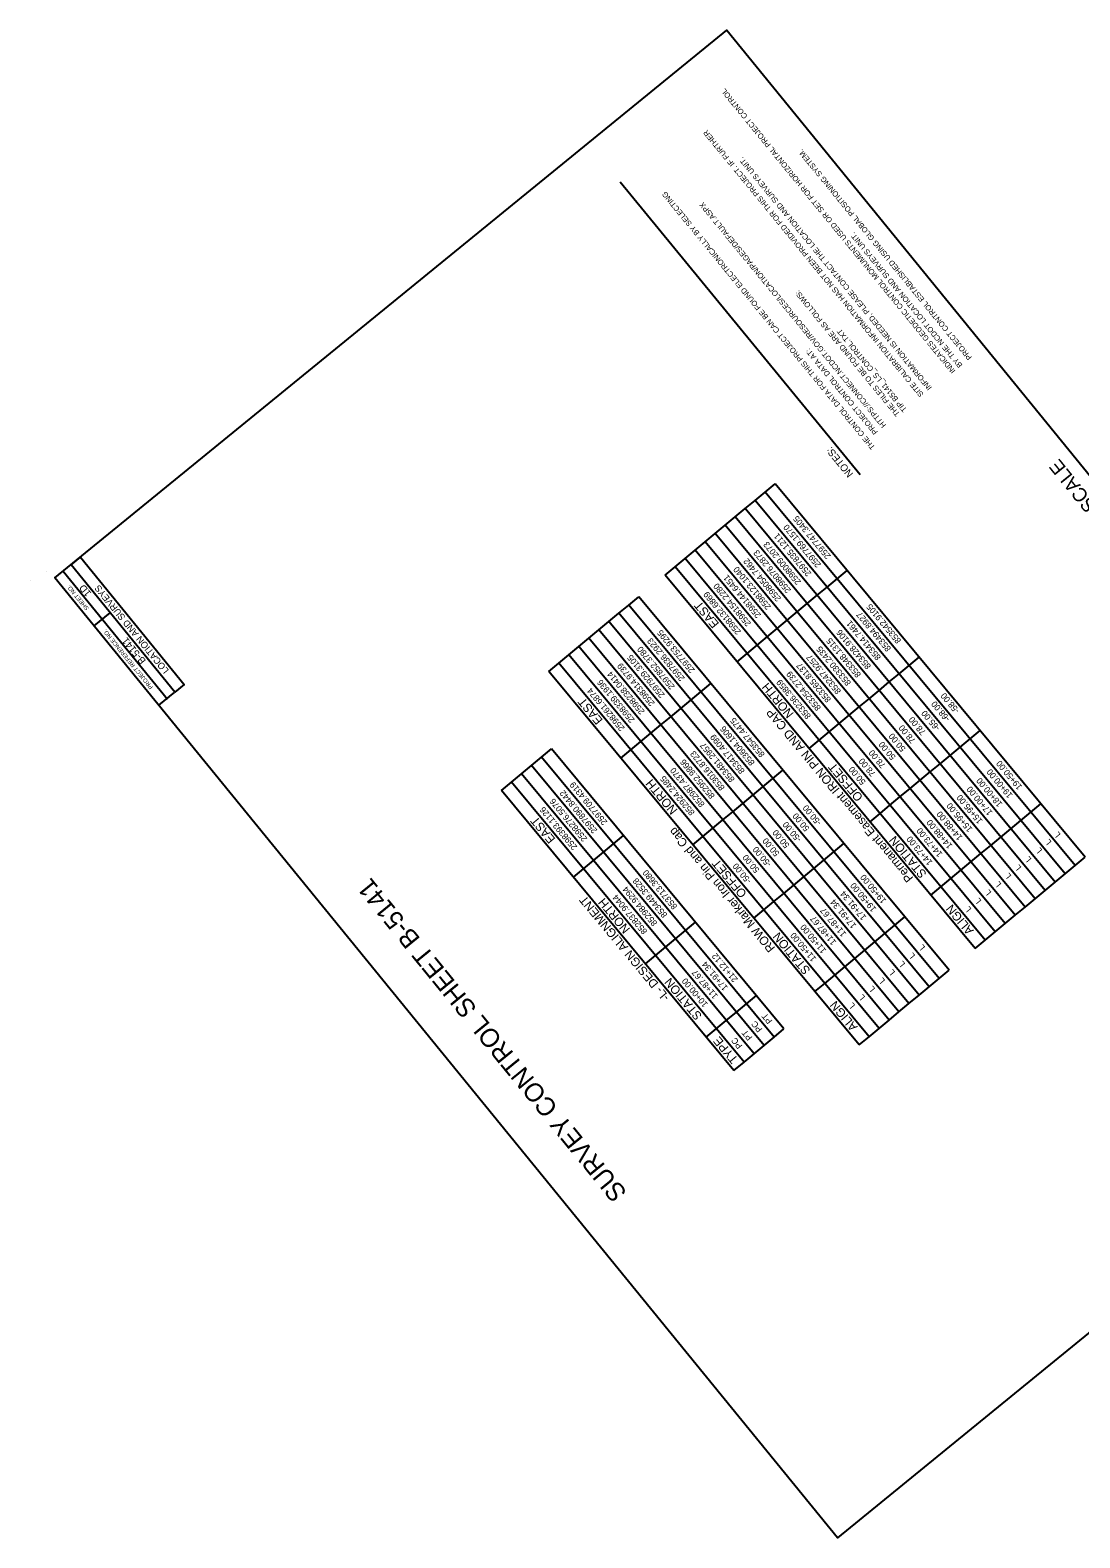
# Model space of a CAD drawing. Extents: x 2596159 to 2598075, y 851667 to 853493.
# Drawn here: x 2596159 to 2597430, y 851667 to 853493 of the extents above; entities that cross this region are included whole.
import ezdxf

# ---------------------------------------------------------------- set-up
doc = ezdxf.new("R2010")
doc.units = 0
for name, color, linetype in [('CTL Sheet Notes CELL', 7, 'Continuous'), ('CTL Sheet Table Cell', 7, 'Continuous'), ('CTL Sheet Text', 7, 'Continuous'), ('Old_Level_1', 7, 'Continuous'), ('Old_Level_18', 7, 'Continuous'), ('Old_Level_40', 7, 'Continuous'), ('Old_Level_44', 7, 'Continuous'), ('Old_Level_50', 7, 'Continuous'), ('Old_Level_52', 7, 'Continuous')]:
    doc.layers.add(name, color=color, linetype=linetype)

msp = doc.modelspace()

# ---------------------------------------------------------------- linework, layer by layer
at = {"layer": 'CTL Sheet Notes CELL'}
msp.add_line((2597164.2, 852954.1), (2596873.5, 853308.6), dxfattribs=at)
at = {"layer": 'CTL Sheet Table Cell'}
for p, q in [((2597049.3, 852933.3), (2597061.4, 852943.4)), ((2597437, 852491), (2597061.4, 852943.4)), ((2597025, 852913.2), (2597037.2, 852923.2)), ((2597037.2, 852923.2), (2597049.3, 852933.3)), ((2597412.8, 852470.9), (2597037.2, 852923.2)), ((2597424.9, 852480.9), (2597049.3, 852933.3)), ((2597000.8, 852893.1), (2597012.9, 852903.1)), ((2597012.9, 852903.1), (2597025, 852913.2)), ((2597388.6, 852450.8), (2597012.9, 852903.1)), ((2597400.7, 852460.8), (2597025, 852913.2)), ((2596976.6, 852872.9), (2596988.7, 852883)), ((2596988.7, 852883), (2597000.8, 852893.1)), ((2597364.3, 852430.6), (2596988.7, 852883)), ((2597376.5, 852440.7), (2597000.8, 852893.1)), ((2596952.3, 852852.8), (2596964.5, 852862.9)), ((2596964.5, 852862.9), (2596976.6, 852872.9)), ((2597340.1, 852410.5), (2596964.5, 852862.9)), ((2597352.2, 852420.6), (2596976.6, 852872.9)), ((2596940.2, 852842.8), (2596952.3, 852852.8)), ((2597328, 852400.5), (2596952.3, 852852.8)), ((2596928.1, 852832.7), (2596940.2, 852842.8)), ((2597303.8, 852380.3), (2596928.1, 852832.7)), ((2597315.9, 852390.4), (2596940.2, 852842.8)), ((2597124.4, 852818.2), (2597136.5, 852828.3)), ((2597136.5, 852828.3), (2597148.6, 852838.4)), ((2597100.1, 852798.1), (2597112.2, 852808.2)), ((2597112.2, 852808.2), (2597124.4, 852818.2)), ((2596872.1, 852786.4), (2596884.2, 852796.4)), ((2596884.2, 852796.4), (2596896.4, 852806.5)), ((2597259.9, 852344), (2596884.2, 852796.4)), ((2597272, 852354.1), (2596896.4, 852806.5)), ((2597088, 852788), (2597100.1, 852798.1)), ((2596847.9, 852766.2), (2596860, 852776.3)), ((2596860, 852776.3), (2596872.1, 852786.4)), ((2597235.7, 852323.9), (2596860, 852776.3)), ((2597247.8, 852334), (2596872.1, 852786.4)), ((2597063.8, 852767.9), (2597075.9, 852778)), ((2597075.9, 852778), (2597088, 852788)), ((2596823.7, 852746.1), (2596835.8, 852756.2)), ((2596835.8, 852756.2), (2596847.9, 852766.2)), ((2597211.4, 852303.8), (2596835.8, 852756.2)), ((2597223.5, 852313.9), (2596847.9, 852766.2)), ((2597039.5, 852747.8), (2597051.7, 852757.9)), ((2597051.7, 852757.9), (2597063.8, 852767.9)), ((2596799.4, 852726), (2596811.5, 852736)), ((2596811.5, 852736), (2596823.7, 852746.1)), ((2597187.2, 852283.7), (2596811.5, 852736)), ((2597199.3, 852293.7), (2596823.7, 852746.1)), ((2597015.3, 852727.7), (2597027.4, 852737.7)), ((2597027.4, 852737.7), (2597039.5, 852747.8)), ((2596787.3, 852715.9), (2596799.4, 852726)), ((2597175.1, 852273.6), (2596799.4, 852726)), ((2597211.6, 852713.2), (2597223.7, 852723.3)), ((2597223.7, 852723.3), (2597235.8, 852733.3)), ((2597163, 852263.6), (2596787.3, 852715.9)), ((2596971.5, 852691.4), (2596983.6, 852701.5)), ((2597187.3, 852693.1), (2597199.4, 852703.2)), ((2597199.4, 852703.2), (2597211.6, 852713.2)), ((2596947.2, 852671.3), (2596959.3, 852681.3)), ((2596959.3, 852681.3), (2596971.5, 852691.4)), ((2597163.1, 852673), (2597175.2, 852683)), ((2597175.2, 852683), (2597187.3, 852693.1)), ((2596935.1, 852661.2), (2596947.2, 852671.3)), ((2597138.9, 852652.8), (2597151, 852662.9)), ((2597151, 852662.9), (2597163.1, 852673)), ((2596910.9, 852641.1), (2596923, 852651.2)), ((2596923, 852651.2), (2596935.1, 852661.2)), ((2597126.7, 852642.8), (2597138.9, 852652.8)), ((2597297.5, 852634.4), (2597309.6, 852644.5)), ((2596886.6, 852621), (2596898.8, 852631)), ((2596898.8, 852631), (2596910.9, 852641.1)), ((2597102.5, 852622.7), (2597114.6, 852632.7)), ((2597114.6, 852632.7), (2597126.7, 852642.8)), ((2597285.4, 852624.4), (2597297.5, 852634.4)), ((2596766.2, 852602.1), (2596778.3, 852612.2)), ((2596778.3, 852612.2), (2596790.4, 852622.2)), ((2597060, 852272.9), (2596778.3, 852612.2)), ((2597072.1, 852283), (2596790.4, 852622.2)), ((2596874.5, 852610.9), (2596886.6, 852621)), ((2597261.1, 852604.2), (2597273.2, 852614.3)), ((2597273.2, 852614.3), (2597285.4, 852624.4)), ((2596741.9, 852582), (2596754, 852592)), ((2596754, 852592), (2596766.2, 852602.1)), ((2597035.8, 852252.8), (2596754, 852592)), ((2597047.9, 852262.8), (2596766.2, 852602.1)), ((2597058.7, 852586.4), (2597070.8, 852596.4)), ((2597236.9, 852584.1), (2597249, 852594.2)), ((2597249, 852594.2), (2597261.1, 852604.2)), ((2596729.8, 852571.9), (2596741.9, 852582)), ((2597011.5, 852232.6), (2596729.8, 852571.9)), ((2597023.7, 852242.7), (2596741.9, 852582)), ((2597034.4, 852566.3), (2597046.5, 852576.3)), ((2597046.5, 852576.3), (2597058.7, 852586.4)), ((2597212.6, 852564), (2597224.8, 852574.1)), ((2597224.8, 852574.1), (2597236.9, 852584.1)), ((2597010.2, 852546.1), (2597022.3, 852556.2)), ((2597022.3, 852556.2), (2597034.4, 852566.3)), ((2597188.4, 852543.9), (2597200.5, 852553.9)), ((2597200.5, 852553.9), (2597212.6, 852564)), ((2597371.3, 852545.6), (2597383.4, 852555.6)), ((2596986, 852526), (2596998.1, 852536.1)), ((2596998.1, 852536.1), (2597010.2, 852546.1)), ((2597176.3, 852533.8), (2597188.4, 852543.9)), ((2597347, 852525.4), (2597359.1, 852535.5)), ((2597359.1, 852535.5), (2597371.3, 852545.6)), ((2596865.5, 852507.2), (2596877.6, 852517.2)), ((2596961.7, 852505.9), (2596973.8, 852516)), ((2596973.8, 852516), (2596986, 852526)), ((2597334.9, 852515.4), (2597347, 852525.4)), ((2596853.4, 852497.1), (2596865.5, 852507.2)), ((2597120.3, 852487.5), (2597132.4, 852497.5)), ((2597132.4, 852497.5), (2597144.6, 852507.6)), ((2597310.7, 852495.3), (2597322.8, 852505.3)), ((2597322.8, 852505.3), (2597334.9, 852515.4)), ((2596829.1, 852477), (2596841.2, 852487)), ((2596841.2, 852487), (2596853.4, 852497.1)), ((2597108.2, 852477.4), (2597120.3, 852487.5)), ((2597286.4, 852475.1), (2597298.6, 852485.2)), ((2597298.6, 852485.2), (2597310.7, 852495.3)), ((2597412.8, 852470.9), (2597424.9, 852480.9)), ((2597424.9, 852480.9), (2597437, 852491)), ((2596817, 852466.9), (2596829.1, 852477)), ((2597084, 852457.3), (2597096.1, 852467.3)), ((2597096.1, 852467.3), (2597108.2, 852477.4)), ((2597262.2, 852455), (2597274.3, 852465.1)), ((2597274.3, 852465.1), (2597286.4, 852475.1)), ((2597388.6, 852450.8), (2597400.7, 852460.8)), ((2597400.7, 852460.8), (2597412.8, 852470.9)), ((2597059.7, 852437.2), (2597071.9, 852447.2)), ((2597071.9, 852447.2), (2597084, 852457.3)), ((2597250.1, 852444.9), (2597262.2, 852455)), ((2597376.5, 852440.7), (2597388.6, 852450.8)), ((2597035.5, 852417), (2597047.6, 852427.1)), ((2597047.6, 852427.1), (2597059.7, 852437.2)), ((2597352.2, 852420.6), (2597364.3, 852430.6)), ((2597364.3, 852430.6), (2597376.5, 852440.7)), ((2596952.7, 852402.1), (2596964.8, 852412.2)), ((2597194.1, 852398.6), (2597206.2, 852408.7)), ((2597206.2, 852408.7), (2597218.3, 852418.7)), ((2597328, 852400.5), (2597340.1, 852410.5)), ((2597340.1, 852410.5), (2597352.2, 852420.6)), ((2596928.5, 852382), (2596940.6, 852392.1)), ((2596940.6, 852392.1), (2596952.7, 852402.1)), ((2597169.9, 852378.5), (2597182, 852388.5)), ((2597182, 852388.5), (2597194.1, 852398.6)), ((2597303.8, 852380.3), (2597315.9, 852390.4)), ((2597315.9, 852390.4), (2597328, 852400.5)), ((2596904.2, 852361.9), (2596916.3, 852372)), ((2596916.3, 852372), (2596928.5, 852382)), ((2597157.8, 852368.4), (2597169.9, 852378.5)), ((2597133.5, 852348.3), (2597145.6, 852358.4)), ((2597145.6, 852358.4), (2597157.8, 852368.4)), ((2597259.9, 852344), (2597272, 852354.1)), ((2597109.3, 852328.2), (2597121.4, 852338.2)), ((2597121.4, 852338.2), (2597133.5, 852348.3)), ((2597235.7, 852323.9), (2597247.8, 852334)), ((2597247.8, 852334), (2597259.9, 852344)), ((2597026.5, 852313.3), (2597038.6, 852323.3)), ((2597223.5, 852313.9), (2597235.7, 852323.9)), ((2597002.2, 852293.2), (2597014.4, 852303.2)), ((2597014.4, 852303.2), (2597026.5, 852313.3)), ((2597199.3, 852293.7), (2597211.4, 852303.8)), ((2597211.4, 852303.8), (2597223.5, 852313.9)), ((2596978, 852273), (2596990.1, 852283.1)), ((2596990.1, 852283.1), (2597002.2, 852293.2)), ((2597060, 852272.9), (2597072.1, 852283)), ((2597175.1, 852273.6), (2597187.2, 852283.7)), ((2597187.2, 852283.7), (2597199.3, 852293.7)), ((2597035.8, 852252.8), (2597047.9, 852262.8)), ((2597047.9, 852262.8), (2597060, 852272.9)), ((2597163, 852263.6), (2597175.1, 852273.6)), ((2597011.5, 852232.6), (2597023.7, 852242.7)), ((2597023.7, 852242.7), (2597035.8, 852252.8))]:
    msp.add_line(p, q, dxfattribs=at)
at = {"layer": 'Old_Level_1'}
msp.add_line((2596179.2, 852837.4), (2596179.2, 852837.4), dxfattribs=at)
at = {"layer": 'Old_Level_18'}
msp.add_lwpolyline([(2596922.8, 851929.1), (2596189, 852829.3), (2597002.9, 853492.7), (2597950.7, 852330), (2597136.8, 851666.6), (2596922.8, 851929.1)], dxfattribs=at)
at = {"layer": 'Old_Level_40'}
for p, q in [((2596325.2, 852682.2), (2596198.8, 852837.2)), ((2596236.5, 852771.2), (2596255.8, 852787)), ((2596314.8, 852675.1), (2596334.1, 852690.9))]:
    msp.add_line(p, q, dxfattribs=at)
msp.add_lwpolyline([(2596334.1, 852690.9), (2596208.5, 852845.1), (2596219.9, 852854.4), (2596345.5, 852700.2)], close=True, dxfattribs=at)
at = {"layer": 'Old_Level_50'}
msp.add_line((2596158.9, 852826.7), (2596158.9, 852826.7), dxfattribs=at)
at = {"layer": 'Old_Level_52'}
msp.add_line((2596179.2, 852837.4), (2596179.2, 852837.4), dxfattribs=at)

# ---------------------------------------------------------------- texts
at = {"layer": 'CTL Sheet Notes CELL'}
for s, height, rotation, p in [('INDICATES GEODETIC CONTROL MONUMENTS USED OR SET FOR HORIZONTAL PROJECT CONTROL', 6.52, 129.2489, (2597280.3, 853080.2)), ('SITE CALIBRATION INFORMATION HAS NOT BEEN PROVIDED FOR THIS PROJECT. IF FURTHER', 6.52, 129.3541, (2597241.7, 853051.7)), ('PROJECT CONTROL ESTABLISHED USING GLOBAL POSITIONING SYSTEM.', 6.52, 129.2489, (2597300.2, 853096.5)), ('INFORMATION IS NEEDED, PLEASE CONTACT THE LOCATION AND SURVEYS UNIT.', 6.52, 129.3541, (2597251.6, 853059.8)), ('   THE CONTROL DATA FOR THIS PROJECT CAN BE FOUND ELECTRONICALLY BY SELECTING', 6.52, 129.3541, (2597187.8, 852982)), ('HTTPS://CONNECT.NCDOT.GOV/RESOURCES/LOCATION/PAGES/DEFAULT.ASPX', 6.52, 129.3541, (2597196.2, 853014.4)), ('BY THE NCDOT LOCATION AND SURVEYS UNIT.', 6.52, 129.2489, (2597288.7, 853087.1)), ('THE FILES TO BE FOUND ARE AS FOLLOWS:', 6.52, 129.3541, (2597212.9, 853028.1)), ('TIP B5141_LS_CONTROL.TXT', 6.52, 129.3541, (2597221.4, 853033.4)), ('PROJECT CONTROL DATA AT:', 6.52, 129.3541, (2597186.2, 853006.2)), ('NOTES:', 8.69, 129.2489, (2597156.5, 852955.4)), ('EAST', 10.5, 129.7067, (2596994, 852773.9)), ('NORTH', 10.5, 129.7067, (2597084.5, 852664.9)), ('EAST', 10.5, 129.7067, (2596853.2, 852657.1)), ('Permanent Easement IRON PIN AND CAP', 10.5, 129.7067, (2597229.3, 852465.9)), ('OFFSET', 10.5, 129.7067, (2597168.4, 852563.9)), ('NORTH', 10.5, 129.7067, (2596943.7, 852548.1)), ('EAST', 10.5, 129.7067, (2596795.7, 852513.1)), ('ROW Marker Iron Pin and Cap', 10.5, 129.7067, (2597061.9, 852381.2)), ('STATION', 10.5, 129.7067, (2597245.5, 852471)), ('OFFSET', 10.5, 129.7067, (2597027.6, 852447.1)), ('-L- DESIGN ALIGNMENT', 10.5, 129.7067, (2596934.1, 852321.8)), ('NORTH', 10.5, 129.7067, (2596886.2, 852404.1)), ('ALIGN', 10.5, 129.7067, (2597302.5, 852402.3)), ('STATION', 10.5, 129.7067, (2597104.7, 852354.3)), ('STATION', 10.5, 129.7067, (2596973.4, 852299.1)), ('ALIGN', 10.5, 129.7067, (2597161.8, 852285.6)), ('TYPE', 10.5, 129.7067, (2597017.1, 852246.5))]:
    msp.add_text(s, height=height, rotation=rotation, dxfattribs=at).set_placement(p)
at = {"layer": 'CTL Sheet Text'}
for s, p in [('2597747.3405', (2597129.3, 852856)), ('2597835.1211', (2597105.7, 852834.9)), ('2597769.1570', (2597117.4, 852845.6)), ('2598076.2873', (2597081.1, 852814.6)), ('2598009.2073', (2597093.2, 852824.7)), ('2598054.7462', (2597069, 852804.5)), ('2598144.6451', (2597044.7, 852784.4)), ('2598123.1040', (2597056.8, 852794.5)), ('2598132.6869', (2597020.5, 852764.3)), ('2598154.2280', (2597032.6, 852774.3)), ('853542.9105', (2597214.5, 852753.6)), ('853414.7461', (2597190.1, 852733.4)), ('853494.8927', (2597202.3, 852743.9)), ('2597836.2923', (2596952.4, 852707.9)), ('2597753.9295', (2596964.5, 852717.9)), ('853348.1315', (2597165.9, 852712.4)), ('853428.9106', (2597178, 852722.5)), ('2597929.3105', (2596928.2, 852687.8)), ('2597852.3780', (2596940.3, 852697.8)), ('853247.9257', (2597141.7, 852692.3)), ('853330.2435', (2597153.8, 852702.4)), ('2598314.9739', (2596916.1, 852677.7)), ('853265.8137', (2597129.6, 852682.3)), ('2598339.1936', (2596891.8, 852657.6)), ('2598238.0414', (2596903.9, 852667.6)), ('853236.3859', (2597105.3, 852662.1)), ('853254.2739', (2597117.4, 852672.2)), ('2598261.6874', (2596879.7, 852647.5)), ('-58.00', (2597285.2, 852669)), ('-65.00', (2597261.7, 852647.7)), ('-68.00', (2597273.7, 852659)), ('853604.1606', (2597037.2, 852605.7)), ('853547.4475', (2597049.4, 852615.8)), ('78.00', (2597232.1, 852632.7)), ('78.00', (2597244.3, 852642.7)), ('853481.2957', (2597013, 852585.6)), ('853417.4099', (2597025.1, 852595.7)), ('50.00', (2597207.9, 852612.6)), ('50.00', (2597220, 852622.6)), ('852952.9866', (2596988.8, 852565.5)), ('853016.8723', (2597000.9, 852575.5)), ('78.00', (2597183.7, 852592.4)), ('78.00', (2597195.8, 852602.5)), ('19+50.00', (2597361.1, 852576.4)), ('852924.2485', (2596964.5, 852545.4)), ('852987.4370', (2596976.6, 852555.4)), ('50.00', (2597171.6, 852582.4)), ('19+00.00', (2597349.5, 852566.3)), ('2597890.8442', (2596846.4, 852523.6)), ('2597709.4319', (2596858.6, 852533.7)), ('17+00.00', (2597325.2, 852545.3)), ('18+00.00', (2597337.1, 852555.6)), ('2598276.5076', (2596834.3, 852513.6)), ('-50.00', (2597118, 852533.2)), ('15+95.00', (2597300.9, 852525.2)), ('15+95.00', (2597313.1, 852535.2)), ('2598393.1126', (2596822.2, 852503.5)), ('-50.00', (2597093.7, 852513)), ('50.00', (2597103.5, 852526)), ('14+88.00', (2597276.7, 852505)), ('14+88.00', (2597288.8, 852515.1)), ('50.00', (2597079.2, 852505.8)), ('14+73.00', (2597252.5, 852484.9)), ('14+73.00', (2597264.6, 852495)), ('L', (2597407.7, 852518.5)), ('-50.00', (2597057.4, 852482.9)), ('50.00', (2597067.1, 852495.8)), ('L', (2597385.5, 852499.5)), ('L', (2597396.7, 852509.5)), ('-50.00', (2597033.1, 852462.7)), ('50.00', (2597042.9, 852475.7)), ('L', (2597360.1, 852478.5)), ('L', (2597372.3, 852488.6)), ('853449.3528', (2596931.3, 852421.5)), ('853713.3680', (2596943.4, 852431.5)), ('19+50.00', (2597196.5, 852438.6)), ('L', (2597335.9, 852458.4)), ('L', (2597348, 852468.5)), ('852837.9044', (2596907, 852401.4)), ('852984.9294', (2596919.1, 852411.4)), ('17+91.34', (2597172.3, 852418.5)), ('19+50.00', (2597184.4, 852428.5)), ('L', (2597323.8, 852448.3)), ('11+87.67', (2597148, 852398.3)), ('17+91.34', (2597160.2, 852408.4)), ('L', (2597299.6, 852428.2)), ('L', (2597311.7, 852438.3)), ('11+50.00', (2597123.8, 852378.2)), ('11+87.67', (2597135.9, 852388.3)), ('11+50.00', (2597111.7, 852368.2)), ('21+12.12', (2597016.7, 852343.2)), ('L', (2597231.5, 852371.8)), ('L', (2597243.6, 852381.9)), ('11+87.67', (2596992.5, 852323.1)), ('17+91.34', (2597004.6, 852333.1)), ('L', (2597207.2, 852351.7)), ('L', (2597219.4, 852361.8)), ('10+00.00', (2596980.4, 852313)), ('L', (2597183, 852331.6)), ('L', (2597195.1, 852341.6)), ('L', (2597158.8, 852311.4)), ('L', (2597170.9, 852321.5)), ('PT ', (2597058.5, 852292.9)), ('PT ', (2597034.3, 852272.8)), ('PC ', (2597046.4, 852282.8)), ('PC ', (2597022.2, 852262.7))]:
    msp.add_text(s, height=7.5, rotation=129.7067, dxfattribs=at).set_placement(p)
at = {"layer": 'Old_Level_40'}
msp.add_text('NOTE: DRAWING NOT TO SCALE', height=16.875, rotation=129.0782, dxfattribs=at).set_placement((2597629.6, 852698.1))
at = {"layer": 'Old_Level_44'}
for s, height, p in [('SHEET NO.', 5, (2596230.4, 852792.5)), ('1D', 8.64, (2596233.5, 852810.8)), ('LOCATION AND SURVEYS', 8, (2596327.4, 852717.4)), ('PROJECT REFERENCE NO.', 5, (2596308.1, 852697)), ('B-5141', 8.64, (2596299.6, 852729.1)), ('SURVEY CONTROL SHEET B-5141', 22.5, (2596882.8, 852085))]:
    msp.add_text(s, height=height, rotation=129.1835, dxfattribs=at).set_placement(p)

doc.saveas('drawing.dxf')
